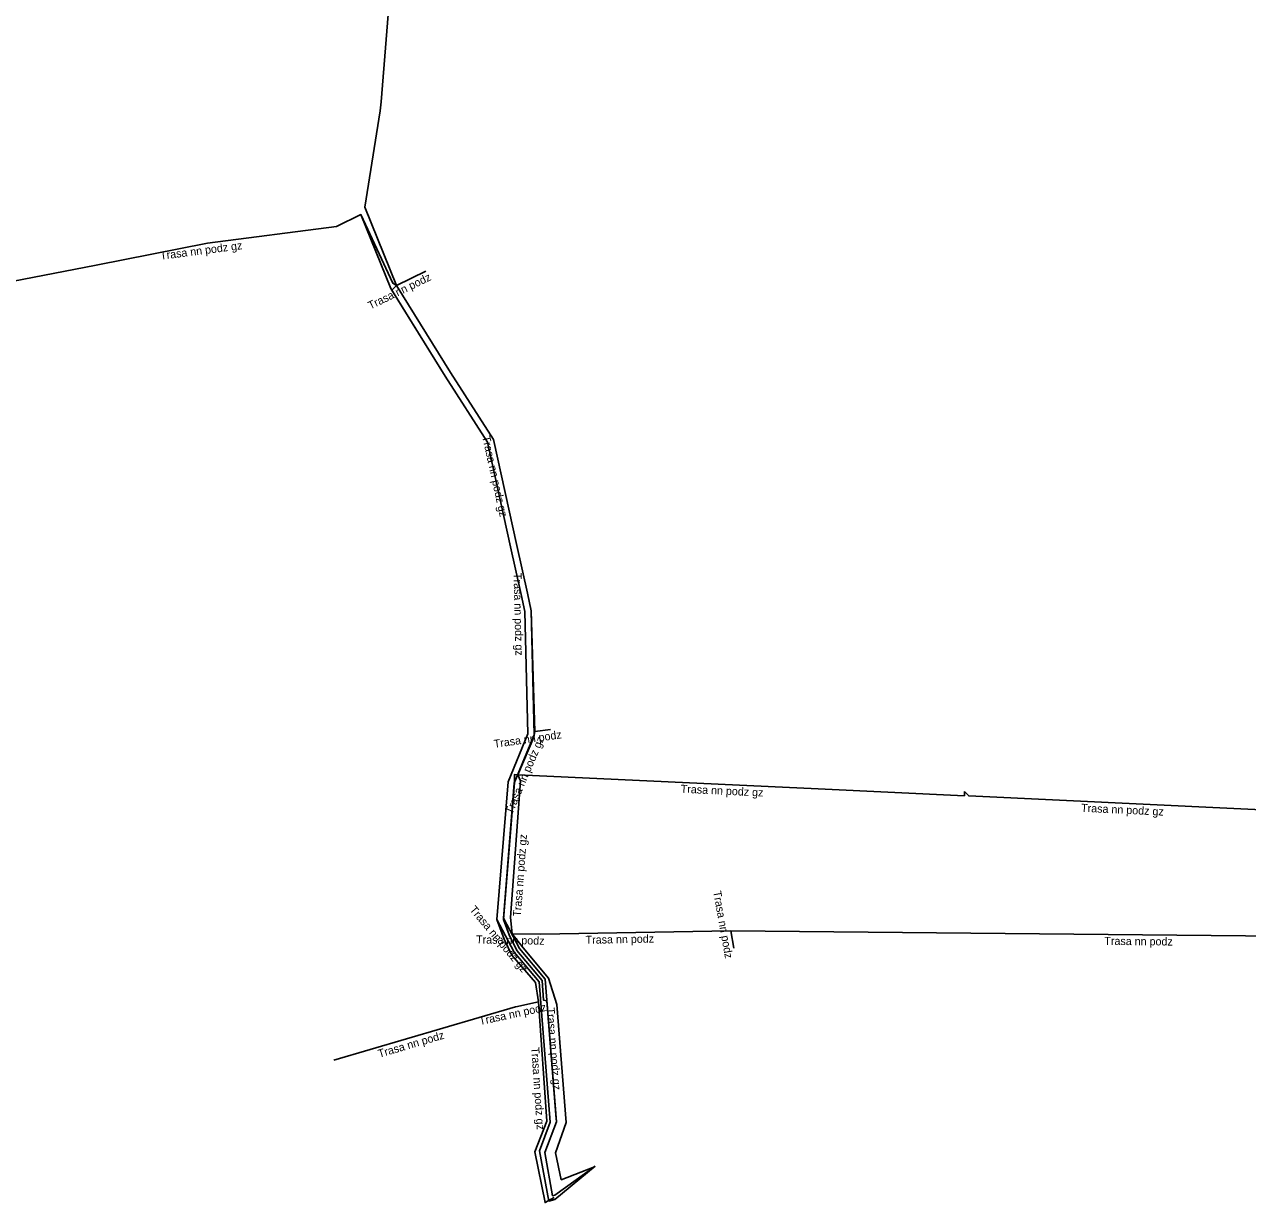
# Model space of a CAD drawing. Extents: x -778200 to -777730, y -1024936 to -1024518.
# Drawn here: x -778010.2 to -777933.8, y -1024872.9 to -1024799.4 of the extents above; entities that cross this region are included whole.
import ezdxf

# ---------------------------------------------------------------- set-up
doc = ezdxf.new("R2010")
doc.units = 0
for name, color, linetype in [('Popiskový text - Ostatní atributy Trasy', 7, 'Continuous'), ('Spojnice NN', 7, 'Continuous'), ('Spojnice VN', 7, 'Continuous')]:
    doc.layers.add(name, color=color, linetype=linetype)

msp = doc.modelspace()

# ---------------------------------------------------------------- linework, layer by layer
at = {"layer": 'Spojnice NN'}
for points in [[(-777986.982, -1024815.651), (-777988.956, -1024810.759), (-777987.991, -1024804.744), (-777987.946, -1024804.189), (-777987.278, -1024795.861), (-777984.699, -1024785.681), (-777984.386, -1024783.71), (-777983.915, -1024782.626), (-777982.282, -1024778.873), (-777978.5, -1024779.714), (-777977.91, -1024779.356), (-777974.257, -1024777.202)], [(-778011.641, -1024815.537), (-778005.741, -1024814.381), (-777998.782, -1024813.016), (-777990.723, -1024811.965), (-777989.197, -1024811.228), (-777987.219, -1024815.519), (-777986.982, -1024815.651)], [(-777985.149, -1024814.76), (-777986.982, -1024815.651)], [(-777986.982, -1024815.651), (-777987.268, -1024815.948), (-777983.943, -1024821.31), (-777981.303, -1024825.426), (-777979.853, -1024831.977), (-777979.195, -1024834.953), (-777978.962, -1024836.006), (-777978.783, -1024843.64), (-777980.014, -1024846.635), (-777980.706, -1024855.244), (-777980.258, -1024856.455), (-777979.78, -1024857.456), (-777978.301, -1024859.159), (-777978.108, -1024860.38)], [(-777978.335, -1024843.506), (-777978.564, -1024835.958), (-777978.805, -1024834.867), (-777979.463, -1024831.891), (-777980.927, -1024825.27), (-777983.605, -1024821.096), (-777986.982, -1024815.651)], [(-777979.397, -1024846.194), (-777978.404, -1024843.844), (-777978.335, -1024843.506)], [(-777978.335, -1024843.506), (-777977.354, -1024843.366)], [(-777979.39, -1024846.194), (-777979.613, -1024846.184), (-777979.601, -1024846.684), (-777980.303, -1024855.23), (-777979.944, -1024856.201), (-777979.464, -1024857.168), (-777977.88, -1024859.047), (-777977.793, -1024860.28), (-777977.584, -1024860.31), (-777977.031, -1024867.436), (-777976.986, -1024867.87)], [(-777979.748, -1024856.123), (-777979.87, -1024855.11), (-777979.227, -1024846.579), (-777979.397, -1024846.194)], [(-777951.497, -1024847.251), (-777951.509, -1024847.51), (-777960.652, -1024847.069), (-777979.39, -1024846.194)], [(-777929.016, -1024848.582), (-777951.244, -1024847.522), (-777951.497, -1024847.251)], [(-777977.957, -1024856.16), (-777966.107, -1024855.935)], [(-777966.107, -1024855.935), (-777921.112, -1024856.385), (-777921.029, -1024864.36)], [(-777966.107, -1024855.935), (-777965.913, -1024857.016)], [(-777974.584, -1024870.632), (-777974.607, -1024870.68), (-777976.688, -1024871.486), (-777977.046, -1024869.812), (-777976.374, -1024867.9), (-777976.971, -1024860.549), (-777977.494, -1024858.905), (-777979.078, -1024857.008), (-777979.748, -1024856.123)], [(-777979.748, -1024856.123), (-777977.957, -1024856.16)], [(-777979.54, -1024860.689), (-777979.52, -1024860.683), (-777978.108, -1024860.38)], [(-777978.108, -1024860.38), (-777977.599, -1024867.825), (-777978.331, -1024869.737), (-777977.704, -1024872.905), (-777977.123, -1024872.586)], [(-777990.894, -1024864.026), (-777990.885, -1024864.023), (-777979.54, -1024860.689)]]:
    msp.add_lwpolyline(points, dxfattribs=at)
at = {"layer": 'Spojnice VN'}
for points in [[(-777974.583, -1024870.632), (-777977.089, -1024872.452), (-777977.244, -1024872.477), (-777977.71, -1024869.772), (-777976.981, -1024867.866), (-777977.686, -1024858.967), (-777979.297, -1024857.056), (-777980.298, -1024855.16), (-777979.622, -1024846.731), (-777978.381, -1024843.714), (-777978.564, -1024835.958), (-777978.805, -1024834.867), (-777979.463, -1024831.891), (-777980.927, -1024825.27), (-777983.605, -1024821.096), (-777986.982, -1024815.651), (-777988.956, -1024810.759), (-777987.991, -1024804.744), (-777987.946, -1024804.189), (-777987.278, -1024795.861)], [(-778011.641, -1024815.537), (-778005.741, -1024814.381), (-777998.782, -1024813.016), (-777990.723, -1024811.965), (-777989.197, -1024811.228), (-777987.34, -1024815.833), (-777983.943, -1024821.31), (-777981.303, -1024825.426), (-777979.853, -1024831.977), (-777979.195, -1024834.953), (-777978.962, -1024836.006), (-777978.783, -1024843.64), (-777980.014, -1024846.635), (-777980.706, -1024855.244), (-777979.631, -1024857.28), (-777978.074, -1024859.127), (-777977.379, -1024867.898), (-777978.059, -1024869.675), (-777977.464, -1024872.816), (-777977.089, -1024872.707), (-777974.583, -1024870.632)]]:
    msp.add_lwpolyline(points, dxfattribs=at)

# ---------------------------------------------------------------- texts
at = {"layer": 'Popiskový text - Ostatní atributy Trasy'}
for s, rotation, p in [('Trasa nn podz gz', 7.43019, (-778001.709, -1024814.053)), ('Trasa nn podz', 25.92385, (-777988.613, -1024817.166)), ('Trasa nn podz gz', 282.46878, (-777981.633, -1024825.09)), ('Trasa nn podz gz', 271.34321, (-777979.668, -1024833.606)), ('Trasa nn podz', 8.12193, (-777980.869, -1024844.524)), ('Trasa nn podz gz', 67.10508, (-777979.75, -1024848.7)), ('Trasa nn podz gz', 357.32795, (-777969.239, -1024847.319)), ('Trasa nn podz gz', 357.27044, (-777944.235, -1024848.507)), ('Trasa nn podz gz', 85.69311, (-777979.215, -1024855.075)), ('Trasa nn podz', 280.17419, (-777967.206, -1024853.492)), ('Trasa nn podz gz', 310.13094, (-777982.446, -1024854.639)), ('Trasa nn podz', 358.8165, (-777982.013, -1024856.726)), ('Trasa nn podz', 1.08776, (-777975.166, -1024856.757)), ('Trasa nn podz', 359.427, (-777942.776, -1024856.819)), ('Trasa nn podz', 12.11138, (-777981.765, -1024861.83)), ('Trasa nn podz gz', 274.64687, (-777977.607, -1024860.753)), ('Trasa nn podz', 16.37819, (-777988.053, -1024863.868)), ('Trasa nn podz gz', 273.91303, (-777978.565, -1024863.224))]:
    msp.add_text(s, height=0.5, rotation=rotation, dxfattribs=at).set_placement(p)

doc.saveas('drawing.dxf')
